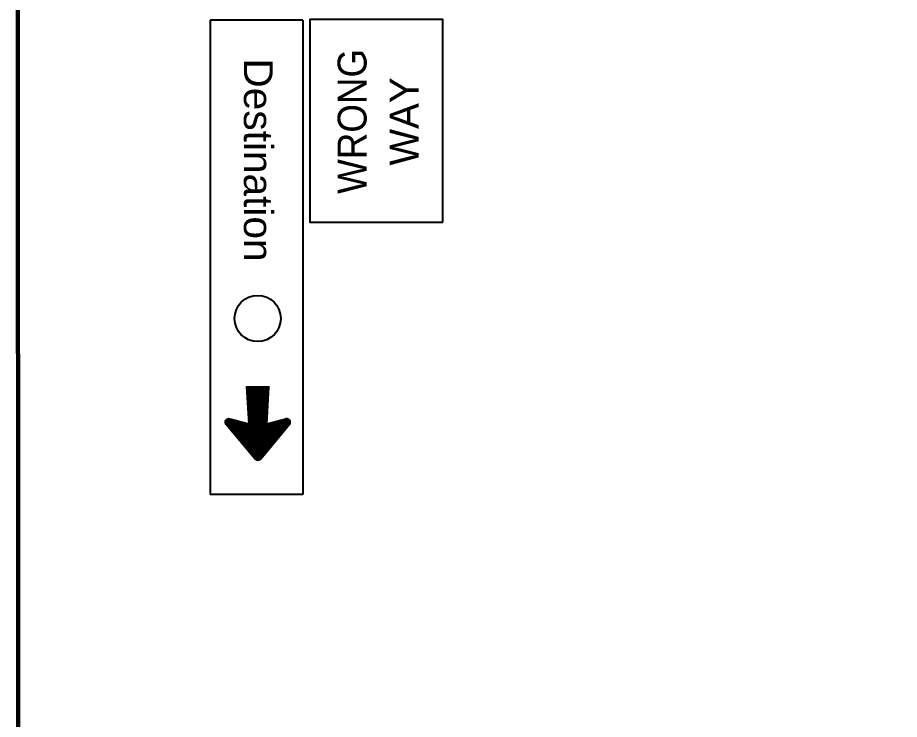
# Model space of a CAD drawing. Extents: x 1081 to 1936, y -630 to -24.
# Drawn here: x 1137.9 to 1229.4, y -331.3 to -258.5 of the extents above; entities that cross this region are included whole.
import ezdxf
from ezdxf.enums import TextEntityAlignment as Align

# ---------------------------------------------------------------- set-up
doc = ezdxf.new("R2010")
doc.units = 0
doc.layers.add('1', color=7, linetype='Continuous', lineweight=53)

msp = doc.modelspace()

# ---------------------------------------------------------------- linework, layer by layer
at = {"layer": '1', "lineweight": 40}
for p, q in [((1157.853, -258.811), (1157.853, -308.011)), ((1167.453, -258.811), (1157.853, -258.811)), ((1167.453, -258.811), (1167.453, -308.011)), ((1161.614, -296.818), (1163.942, -296.818)), ((1161.626, -296.938), (1163.929, -296.938)), ((1161.638, -297.058), (1163.918, -297.058)), ((1161.638, -297.178), (1163.918, -297.178)), ((1161.649, -297.298), (1163.906, -297.298)), ((1162.754, -296.818), (1163.942, -296.818)), ((1162.754, -296.938), (1163.929, -296.938)), ((1162.754, -297.058), (1163.918, -297.058)), ((1162.754, -297.178), (1163.918, -297.178)), ((1162.754, -297.298), (1163.906, -297.298)), ((1161.662, -297.418), (1163.906, -297.418)), ((1161.662, -297.538), (1163.894, -297.538)), ((1161.674, -297.658), (1163.894, -297.658)), ((1161.674, -297.778), (1163.881, -297.778)), ((1161.686, -297.898), (1163.881, -297.898)), ((1161.697, -298.018), (1163.87, -298.018)), ((1161.697, -298.138), (1163.87, -298.138)), ((1162.754, -297.418), (1163.906, -297.418)), ((1162.754, -297.538), (1163.894, -297.538)), ((1162.754, -297.658), (1163.894, -297.658)), ((1162.754, -297.778), (1163.881, -297.778)), ((1162.754, -297.898), (1163.881, -297.898)), ((1162.754, -298.018), (1163.87, -298.018)), ((1162.754, -298.138), (1163.87, -298.138)), ((1161.71, -298.258), (1163.858, -298.258)), ((1161.722, -298.378), (1163.858, -298.378)), ((1161.722, -298.498), (1163.846, -298.498)), ((1161.734, -298.618), (1163.846, -298.618)), ((1161.734, -298.738), (1163.833, -298.738)), ((1161.745, -298.858), (1163.822, -298.858)), ((1161.758, -298.978), (1163.822, -298.978)), ((1161.758, -299.098), (1163.81, -299.098)), ((1162.754, -298.258), (1163.858, -298.258)), ((1162.754, -298.378), (1163.858, -298.378)), ((1162.754, -298.498), (1163.846, -298.498)), ((1162.754, -298.618), (1163.846, -298.618)), ((1162.754, -298.738), (1163.833, -298.738)), ((1162.754, -298.858), (1163.822, -298.858)), ((1162.754, -298.978), (1163.822, -298.978)), ((1162.754, -299.098), (1163.81, -299.098)), ((1161.77, -299.218), (1163.81, -299.218)), ((1161.77, -299.338), (1163.798, -299.338)), ((1161.77, -299.458), (1163.798, -299.458)), ((1161.782, -299.578), (1163.785, -299.578)), ((1161.793, -299.698), (1163.785, -299.698)), ((1161.793, -299.818), (1163.774, -299.818)), ((1161.806, -299.938), (1163.774, -299.938)), ((1161.806, -300.058), (1163.762, -300.058)), ((1162.754, -299.218), (1163.81, -299.218)), ((1162.754, -299.338), (1163.798, -299.338)), ((1162.754, -299.458), (1163.798, -299.458)), ((1162.754, -299.578), (1163.785, -299.578)), ((1162.754, -299.698), (1163.785, -299.698)), ((1162.754, -299.818), (1163.774, -299.818)), ((1162.754, -299.938), (1163.774, -299.938)), ((1162.754, -300.058), (1163.762, -300.058)), ((1159.406, -300.538), (1161.409, -300.538)), ((1159.454, -300.298), (1160.51, -300.298)), ((1159.538, -300.778), (1166.018, -300.778)), ((1159.634, -300.898), (1165.922, -300.898)), ((1161.818, -300.178), (1163.762, -300.178)), ((1161.83, -300.298), (1163.75, -300.298)), ((1161.83, -300.418), (1163.75, -300.418)), ((1161.841, -300.538), (1163.737, -300.538)), ((1162.754, -300.178), (1163.762, -300.178)), ((1162.754, -300.298), (1163.75, -300.298)), ((1162.754, -300.418), (1163.75, -300.418)), ((1162.754, -300.538), (1163.737, -300.538)), ((1162.754, -300.658), (1163.737, -300.658)), ((1162.754, -300.778), (1166.018, -300.778)), ((1162.754, -300.898), (1165.922, -300.898)), ((1164.206, -300.538), (1166.149, -300.538)), ((1164.206, -300.538), (1166.149, -300.538)), ((1164.649, -300.418), (1166.149, -300.418)), ((1164.649, -300.418), (1166.149, -300.418)), ((1159.742, -301.018), (1165.826, -301.018)), ((1159.838, -301.138), (1165.73, -301.138)), ((1159.946, -301.258), (1165.621, -301.258)), ((1160.042, -301.378), (1165.525, -301.378)), ((1160.149, -301.498), (1165.429, -301.498)), ((1160.245, -301.618), (1165.333, -301.618)), ((1160.354, -301.738), (1165.226, -301.738)), ((1160.449, -301.858), (1165.13, -301.858)), ((1162.754, -301.018), (1165.826, -301.018)), ((1162.754, -301.138), (1165.73, -301.138)), ((1162.754, -301.258), (1165.621, -301.258)), ((1162.754, -301.378), (1165.525, -301.378)), ((1162.754, -301.498), (1165.429, -301.498)), ((1162.754, -301.618), (1165.333, -301.618)), ((1162.754, -301.738), (1165.226, -301.738)), ((1162.754, -301.858), (1165.13, -301.858)), ((1160.545, -301.978), (1165.034, -301.978)), ((1160.654, -302.098), (1164.926, -302.098)), ((1160.75, -302.218), (1164.83, -302.218)), ((1160.858, -302.338), (1164.734, -302.338)), ((1160.954, -302.458), (1164.638, -302.458)), ((1161.062, -302.578), (1164.53, -302.578)), ((1161.158, -302.698), (1164.434, -302.698)), ((1162.754, -301.978), (1165.034, -301.978)), ((1162.754, -302.098), (1164.926, -302.098)), ((1162.754, -302.218), (1164.83, -302.218)), ((1162.754, -302.338), (1164.734, -302.338)), ((1162.754, -302.458), (1164.638, -302.458)), ((1162.754, -302.578), (1164.53, -302.578)), ((1162.754, -302.698), (1164.434, -302.698)), ((1161.265, -302.818), (1164.338, -302.818)), ((1161.361, -302.938), (1164.242, -302.938)), ((1161.47, -303.058), (1164.134, -303.058)), ((1161.566, -303.178), (1164.038, -303.178)), ((1161.674, -303.298), (1163.942, -303.298)), ((1161.77, -303.418), (1163.846, -303.418)), ((1161.866, -303.538), (1163.737, -303.538)), ((1161.962, -303.658), (1163.641, -303.658)), ((1162.754, -302.818), (1164.338, -302.818)), ((1162.754, -302.938), (1164.242, -302.938)), ((1162.754, -303.058), (1164.134, -303.058)), ((1162.754, -303.178), (1164.038, -303.178)), ((1162.754, -303.298), (1163.942, -303.298)), ((1162.754, -303.418), (1163.846, -303.418)), ((1162.754, -303.538), (1163.737, -303.538)), ((1162.754, -303.658), (1163.641, -303.658)), ((1162.058, -303.778), (1163.545, -303.778)), ((1162.166, -303.898), (1163.438, -303.898)), ((1162.262, -304.018), (1163.341, -304.018)), ((1162.37, -304.138), (1163.245, -304.138)), ((1162.466, -304.258), (1163.149, -304.258)), ((1162.754, -303.778), (1163.545, -303.778)), ((1162.754, -303.898), (1163.438, -303.898)), ((1162.754, -304.018), (1163.341, -304.018)), ((1162.754, -304.138), (1163.245, -304.138)), ((1162.754, -304.258), (1163.149, -304.258)), ((1167.453, -308.011), (1157.853, -308.011))]:
    msp.add_line(p, q, dxfattribs=at)
at = {"layer": '1', "lineweight": 35}
for p, q in [((1162.525, -304.318), (1159.49, -300.73)), ((1166.078, -300.718), (1163.101, -304.318))]:
    msp.add_line(p, q, dxfattribs=at)
at = {"layer": '1', "lineweight": 158}
msp.add_lwpolyline([(1929.57, -30.27), (1137.87, -30.37), (1137.97, -556.37)], dxfattribs=at)
at = {"layer": '1', "lineweight": 40}
msp.add_lwpolyline([(1181.996, -279.735), (1181.996, -258.735), (1168.197, -258.735), (1168.197, -279.735)], close=True, dxfattribs=at)
at = {"layer": '1', "lineweight": 35}
msp.add_lwpolyline([(1159.874, -300.13), (1161.854, -300.658), (1161.614, -296.818), (1163.942, -296.818), (1163.737, -300.67), (1165.694, -300.13)], dxfattribs=at)
at = {"layer": '1', "lineweight": 40}
for points in [[(1159.406, -300.418), (1159.418, -300.418), (1160.954, -300.418)], [(1159.442, -300.658), (1159.454, -300.658), (1161.854, -300.658), (1163.737, -300.658)], [(1159.562, -300.178), (1159.573, -300.178), (1160.066, -300.178)], [(1163.774, -300.658), (1166.101, -300.658), (1166.114, -300.658)], [(1163.774, -300.658), (1166.101, -300.658), (1166.114, -300.658)], [(1165.082, -300.298), (1166.101, -300.298), (1166.114, -300.298)], [(1165.082, -300.298), (1166.101, -300.298), (1166.114, -300.298)], [(1165.514, -300.178), (1165.994, -300.178), (1166.005, -300.178)], [(1165.514, -300.178), (1165.994, -300.178), (1166.005, -300.178)], [(1162.598, -304.378), (1162.573, -304.378), (1162.598, -304.378), (1163.018, -304.378), (1163.018, -304.378)], [(1162.754, -304.378), (1163.018, -304.378), (1163.03, -304.378)]]:
    msp.add_lwpolyline(points, dxfattribs=at)
msp.add_circle((1162.775, -289.737), 2.4, dxfattribs=at)
at = {"layer": '1', "lineweight": 35}
for centre, start, end in [((1159.772, -300.489), 75.11373, 220.25762), ((1165.789, -300.485), 320.43005, 105.55122), ((1162.814, -304.08), 220.25653, 320.40471)]:
    msp.add_arc(centre, 0.372, start, end, dxfattribs=at)

# ---------------------------------------------------------------- texts
at = {"layer": '1'}
for s, rotation, width, p in [('WRONG', 90, 0.95, (1174.075, -269.297)), ('Destination', 270, 1.05, (1161.348, -273.299))]:
    msp.add_text(s, height=3, rotation=rotation, dxfattribs=dict(at, width=width)).set_placement(p, align=Align.CENTER)
msp.add_text('WAY', height=3, rotation=90, dxfattribs=at).set_placement((1179.475, -269.297), align=Align.CENTER)

doc.saveas('drawing.dxf')
